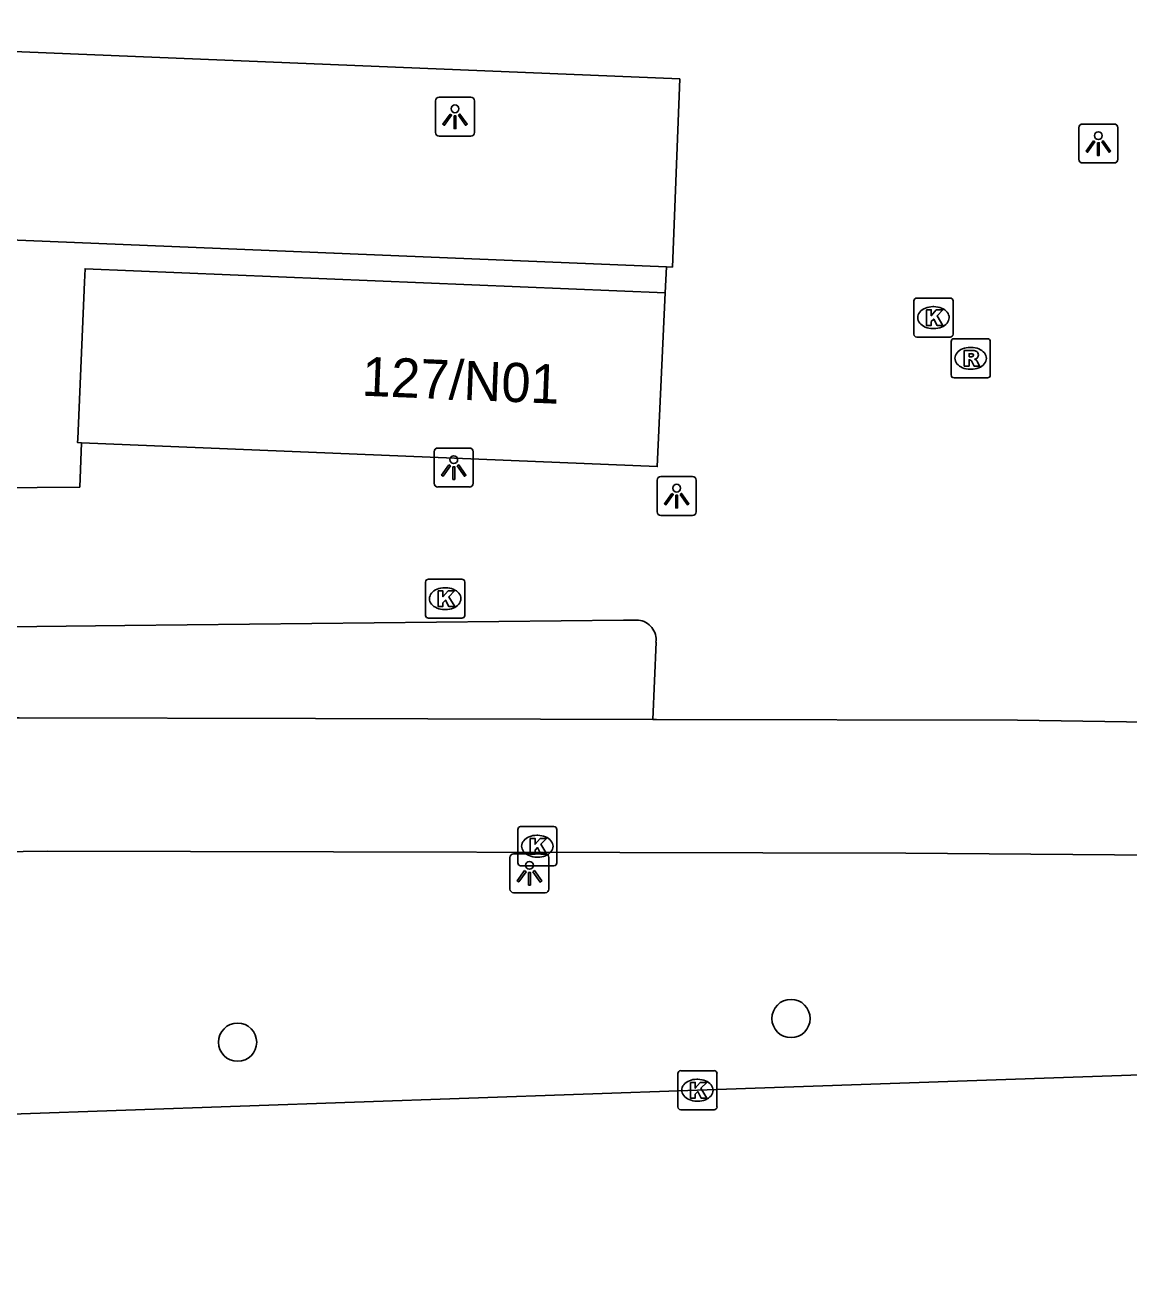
# Model space of a CAD drawing. Extents: x 160891 to 161384, y 386490 to 386907.
# Drawn here: x 161237.19 to 161265.4, y 386500.4 to 386532.6 of the extents above; entities that cross this region are included whole.
import ezdxf

# ---------------------------------------------------------------- set-up
doc = ezdxf.new("R2010")
doc.units = 0
for name, color, linetype in [('IMGEO_Boom', 7, 'Continuous'), ('IMGEO_Fietspad_gesloten', 7, 'Continuous'), ('IMGEO_Kolk', 7, 'Continuous'), ('IMGEO_Lichtpunt', 7, 'Continuous'), ('IMGEO_Pand', 7, 'Continuous'), ('IMGEO_Pand_nummerreeks', 7, 'Continuous'), ('IMGEO_Parkeervlak_open', 7, 'Continuous'), ('IMGEO_Rijbaan_regionaal_gesloten', 7, 'Continuous'), ('IMGEO_Rioolput', 7, 'Continuous'), ('IMGEO_Voetgangersgebied_open', 7, 'Continuous'), ('IMGEO_Voetpad_open', 7, 'Continuous')]:
    doc.layers.add(name, color=color, linetype=linetype)

msp = doc.modelspace()

# ---------------------------------------------------------------- linework, layer by layer
at = {"layer": 'IMGEO_Boom'}
for centre in [(161256.765, 386507.206), (161242.616, 386506.601)]:
    msp.add_circle(centre, 0.489, dxfattribs=at)
at = {"layer": 'IMGEO_Fietspad_gesloten'}
for points in [[(161253.233, 386514.853), (161244.609, 386514.875), (161237.032, 386514.894), (161236.549, 386514.895), (161233.821, 386514.854), (161231.599, 386514.82), (161230.845, 386514.809), (161227.787, 386514.763), (161226.292, 386514.741), (161221.75, 386514.672), (161219.333, 386514.636), (161214.527, 386514.564), (161214.131, 386514.554), (161212.923, 386514.523), (161205.423, 386514.331), (161205.404, 386514.331)], [(161306.554, 386513.058), (161267.578, 386514.754), (161262.551, 386514.831), (161253.325, 386514.853), (161253.233, 386514.853)], [(161109.839, 386506.955), (161116.836, 386508.035), (161123.035, 386508.931), (161127.225, 386509.29), (161167.964, 386510.348), (161215.734, 386511.569), (161215.758, 386511.159), (161222.805, 386511.284), (161237.753, 386511.488), (161259.697, 386511.429), (161267.164, 386511.376), (161306.097, 386509.668), (161311.73, 386509.285), (161311.776, 386509.705), (161313.071, 386509.592)]]:
    msp.add_lwpolyline(points, dxfattribs=at)
at = {"layer": 'IMGEO_Kolk'}
for p, q in [((161259.98, 386525.624), (161260.832, 386525.624)), ((161259.905, 386524.698), (161259.905, 386525.55)), ((161260.393, 386525.404), (161260.418, 386525.404)), ((161260.906, 386525.55), (161260.906, 386524.698)), ((161260.832, 386524.624), (161259.98, 386524.624)), ((161260.416, 386524.844), (161260.391, 386524.844)), ((161247.422, 386517.513), (161247.422, 386518.365)), ((161247.497, 386518.439), (161248.349, 386518.439)), ((161247.91, 386518.219), (161247.935, 386518.219)), ((161248.423, 386518.365), (161248.423, 386517.513)), ((161247.933, 386517.659), (161247.908, 386517.659)), ((161248.349, 386517.439), (161247.497, 386517.439)), ((161249.853, 386512.111), (161250.705, 386512.111)), ((161249.778, 386511.185), (161249.778, 386512.037)), ((161250.266, 386511.891), (161250.291, 386511.891)), ((161250.779, 386512.037), (161250.779, 386511.185)), ((161250.705, 386511.111), (161249.853, 386511.111)), ((161250.289, 386511.331), (161250.264, 386511.331)), ((161253.871, 386504.947), (161253.871, 386505.799)), ((161253.946, 386505.873), (161254.798, 386505.873)), ((161254.359, 386505.653), (161254.384, 386505.653)), ((161254.872, 386505.799), (161254.872, 386504.947)), ((161254.382, 386505.093), (161254.357, 386505.093)), ((161254.798, 386504.873), (161253.946, 386504.873))]:
    msp.add_line(p, q, dxfattribs=at)
for points in [[(161259.98, 386525.624), (161260.832, 386525.624)], [(161259.905, 386524.698), (161259.905, 386525.55)], [(161260.226, 386525.324), (161260.349, 386525.324), (161260.349, 386525.173), (161260.479, 386525.324), (161260.643, 386525.324), (161260.497, 386525.173), (161260.65, 386524.924), (161260.498, 386524.924), (161260.413, 386525.088), (161260.349, 386525.021), (161260.349, 386524.924), (161260.226, 386524.924), (161260.226, 386525.324)], [(161260.906, 386525.55), (161260.906, 386524.698)], [(161260.832, 386524.624), (161259.98, 386524.624)], [(161247.422, 386517.513), (161247.422, 386518.365)], [(161247.497, 386518.439), (161248.349, 386518.439)], [(161248.423, 386518.365), (161248.423, 386517.513)], [(161247.743, 386518.139), (161247.866, 386518.139), (161247.866, 386517.988), (161247.996, 386518.139), (161248.16, 386518.139), (161248.014, 386517.988), (161248.167, 386517.739), (161248.015, 386517.739), (161247.93, 386517.903), (161247.866, 386517.836), (161247.866, 386517.739), (161247.743, 386517.739), (161247.743, 386518.139)], [(161248.349, 386517.439), (161247.497, 386517.439)], [(161249.853, 386512.111), (161250.705, 386512.111)], [(161249.778, 386511.185), (161249.778, 386512.037)], [(161250.099, 386511.811), (161250.222, 386511.811), (161250.222, 386511.66), (161250.352, 386511.811), (161250.516, 386511.811), (161250.37, 386511.66), (161250.523, 386511.411), (161250.371, 386511.411), (161250.286, 386511.575), (161250.222, 386511.508), (161250.222, 386511.411), (161250.099, 386511.411), (161250.099, 386511.811)], [(161250.779, 386512.037), (161250.779, 386511.185)], [(161250.705, 386511.111), (161249.853, 386511.111)], [(161253.871, 386504.947), (161253.871, 386505.799)], [(161253.946, 386505.873), (161254.798, 386505.873)], [(161254.872, 386505.799), (161254.872, 386504.947)], [(161254.192, 386505.573), (161254.315, 386505.573), (161254.315, 386505.422), (161254.445, 386505.573), (161254.609, 386505.573), (161254.463, 386505.422), (161254.616, 386505.173), (161254.464, 386505.173), (161254.379, 386505.337), (161254.315, 386505.27), (161254.315, 386505.173), (161254.192, 386505.173), (161254.192, 386505.573)], [(161254.798, 386504.873), (161253.946, 386504.873)]]:
    msp.add_lwpolyline(points, dxfattribs=at)
for centre, start, end in [((161259.982, 386525.548), 91.552, 178.448), ((161259.982, 386525.548), 91.552, 178.448), ((161260.83, 386525.548), 1.552, 88.448), ((161260.83, 386525.548), 1.552, 88.448), ((161259.982, 386524.7), 181.552, 268.448), ((161259.982, 386524.7), 181.552, 268.448), ((161260.83, 386524.7), 271.552, 358.448), ((161260.83, 386524.7), 271.552, 358.448), ((161247.499, 386518.363), 91.552, 178.448), ((161247.499, 386518.363), 91.552, 178.448), ((161248.347, 386518.363), 1.552, 88.448), ((161248.347, 386518.363), 1.552, 88.448), ((161247.499, 386517.515), 181.552, 268.448), ((161247.499, 386517.515), 181.552, 268.448), ((161248.347, 386517.515), 271.552, 358.448), ((161248.347, 386517.515), 271.552, 358.448), ((161249.855, 386512.035), 91.552, 178.448), ((161249.855, 386512.035), 91.552, 178.448), ((161250.703, 386512.035), 1.552, 88.448), ((161250.703, 386512.035), 1.552, 88.448), ((161249.855, 386511.187), 181.552, 268.448), ((161249.855, 386511.187), 181.552, 268.448), ((161250.703, 386511.187), 271.552, 358.448), ((161250.703, 386511.187), 271.552, 358.448), ((161253.948, 386505.797), 91.552, 178.448), ((161253.948, 386505.797), 91.552, 178.448), ((161254.796, 386505.797), 1.552, 88.448), ((161254.796, 386505.797), 1.552, 88.448), ((161253.948, 386504.949), 181.552, 268.448), ((161253.948, 386504.949), 181.552, 268.448), ((161254.796, 386504.949), 271.552, 358.448), ((161254.796, 386504.949), 271.552, 358.448)]:
    msp.add_arc(centre, 0.0765, start, end, dxfattribs=at)
for centre, major_axis, ratio, start_param, end_param in [((161260.392, 386525.124), (-0.387, 0.002), 0.722429, 4.712389, 7.853982), ((161260.417, 386525.124), (-0.39, 0.002), 0.717154, 1.570796, 4.712389), ((161247.909, 386517.939), (-0.387, 0.002), 0.722429, 4.712389, 7.853982), ((161247.934, 386517.939), (-0.39, 0.002), 0.717154, 1.570796, 4.712389), ((161250.265, 386511.611), (-0.387, 0.002), 0.722429, 4.712389, 7.853982), ((161250.29, 386511.611), (-0.39, 0.002), 0.717154, 1.570796, 4.712389), ((161254.358, 386505.373), (-0.387, 0.002), 0.722429, 4.712389, 7.853982), ((161254.383, 386505.373), (-0.39, 0.002), 0.717154, 1.570796, 4.712389)]:
    msp.add_ellipse(centre, major_axis=major_axis, ratio=ratio, start_param=start_param, end_param=end_param, dxfattribs=at)
at = {"layer": 'IMGEO_Lichtpunt'}
for p, q in [((161248.577, 386530.759), (161247.769, 386530.759)), ((161248.577, 386530.759), (161247.769, 386530.759)), ((161247.675, 386530.664), (161247.675, 386529.857)), ((161247.675, 386530.664), (161247.675, 386529.857)), ((161248.671, 386529.857), (161248.671, 386530.664)), ((161248.671, 386529.857), (161248.671, 386530.664)), ((161264.123, 386529.978), (161264.123, 386529.171)), ((161264.123, 386529.978), (161264.123, 386529.171)), ((161265.025, 386530.073), (161264.217, 386530.073)), ((161265.025, 386530.073), (161264.217, 386530.073)), ((161265.119, 386529.171), (161265.119, 386529.978)), ((161265.119, 386529.171), (161265.119, 386529.978)), ((161247.769, 386529.763), (161248.577, 386529.763)), ((161247.769, 386529.763), (161248.577, 386529.763)), ((161264.217, 386529.077), (161265.025, 386529.077)), ((161264.217, 386529.077), (161265.025, 386529.077)), ((161248.546, 386521.79), (161247.738, 386521.79)), ((161248.546, 386521.79), (161247.738, 386521.79)), ((161247.644, 386521.695), (161247.644, 386520.888)), ((161247.644, 386521.695), (161247.644, 386520.888)), ((161248.64, 386520.888), (161248.64, 386521.695)), ((161248.64, 386520.888), (161248.64, 386521.695)), ((161247.738, 386520.794), (161248.546, 386520.794)), ((161247.738, 386520.794), (161248.546, 386520.794)), ((161253.343, 386520.966), (161253.343, 386520.159)), ((161253.343, 386520.966), (161253.343, 386520.159)), ((161254.245, 386521.061), (161253.437, 386521.061)), ((161254.245, 386521.061), (161253.437, 386521.061)), ((161254.339, 386520.159), (161254.339, 386520.966)), ((161254.339, 386520.159), (161254.339, 386520.966)), ((161253.437, 386520.065), (161254.245, 386520.065)), ((161253.437, 386520.065), (161254.245, 386520.065)), ((161250.481, 386511.418), (161249.673, 386511.418)), ((161250.481, 386511.418), (161249.673, 386511.418)), ((161249.579, 386511.323), (161249.579, 386510.516)), ((161249.579, 386511.323), (161249.579, 386510.516)), ((161250.575, 386510.516), (161250.575, 386511.323)), ((161250.575, 386510.516), (161250.575, 386511.323)), ((161249.673, 386510.422), (161250.481, 386510.422)), ((161249.673, 386510.422), (161250.481, 386510.422))]:
    msp.add_line(p, q, dxfattribs=at)
for points in [[(161248.049, 386530.328), (161248.088, 386530.3), (161247.9, 386530.038), (161247.862, 386530.065), (161248.049, 386530.328)], [(161248.151, 386530.28), (161248.198, 386530.28), (161248.198, 386529.958), (161248.151, 386529.958), (161248.151, 386530.28)], [(161248.261, 386530.3), (161248.299, 386530.327), (161248.486, 386530.065), (161248.447, 386530.037), (161248.261, 386530.3)], [(161264.497, 386529.642), (161264.536, 386529.614), (161264.348, 386529.352), (161264.31, 386529.379), (161264.497, 386529.642)], [(161264.599, 386529.594), (161264.646, 386529.594), (161264.646, 386529.272), (161264.599, 386529.272), (161264.599, 386529.594)], [(161264.709, 386529.614), (161264.747, 386529.641), (161264.934, 386529.379), (161264.895, 386529.351), (161264.709, 386529.614)], [(161248.018, 386521.359), (161248.057, 386521.331), (161247.869, 386521.069), (161247.831, 386521.096), (161248.018, 386521.359)], [(161248.12, 386521.311), (161248.167, 386521.311), (161248.167, 386520.989), (161248.12, 386520.989), (161248.12, 386521.311)], [(161248.23, 386521.331), (161248.268, 386521.358), (161248.455, 386521.096), (161248.416, 386521.068), (161248.23, 386521.331)], [(161253.717, 386520.63), (161253.756, 386520.602), (161253.568, 386520.34), (161253.53, 386520.367), (161253.717, 386520.63)], [(161253.819, 386520.582), (161253.866, 386520.582), (161253.866, 386520.26), (161253.819, 386520.26), (161253.819, 386520.582)], [(161253.929, 386520.602), (161253.967, 386520.629), (161254.154, 386520.367), (161254.115, 386520.339), (161253.929, 386520.602)], [(161249.953, 386510.987), (161249.992, 386510.959), (161249.804, 386510.697), (161249.766, 386510.724), (161249.953, 386510.987)], [(161250.055, 386510.939), (161250.102, 386510.939), (161250.102, 386510.617), (161250.055, 386510.617), (161250.055, 386510.939)], [(161250.165, 386510.959), (161250.203, 386510.986), (161250.39, 386510.724), (161250.351, 386510.696), (161250.165, 386510.959)]]:
    msp.add_lwpolyline(points, dxfattribs=at)
for centre in [(161248.174, 386530.462), (161264.622, 386529.776), (161248.143, 386521.493), (161253.842, 386520.764), (161250.078, 386511.121)]:
    msp.add_circle(centre, 0.0994, dxfattribs=at)
for centre, start, end in [((161247.769, 386530.664), 90, 180), ((161247.769, 386530.664), 90, 180), ((161248.577, 386530.664), 0, 90), ((161248.577, 386530.664), 0, 90), ((161247.769, 386529.857), 180, 270), ((161247.769, 386529.857), 180, 270), ((161248.577, 386529.857), 270, 0), ((161248.577, 386529.857), 270, 360), ((161264.217, 386529.978), 90, 180), ((161264.217, 386529.978), 90, 180), ((161265.025, 386529.978), 0, 90), ((161265.025, 386529.978), 0, 90), ((161264.217, 386529.171), 180, 270), ((161264.217, 386529.171), 180, 270), ((161265.025, 386529.171), 270, 0), ((161265.025, 386529.171), 270, 360), ((161247.738, 386521.695), 90, 180), ((161247.738, 386521.695), 90, 180), ((161248.546, 386521.695), 0, 90), ((161248.546, 386521.695), 0, 90), ((161247.738, 386520.888), 180, 270), ((161247.738, 386520.888), 180, 270), ((161248.546, 386520.888), 270, 0), ((161248.546, 386520.888), 270, 360), ((161253.437, 386520.966), 90, 180), ((161253.437, 386520.966), 90, 180), ((161254.245, 386520.966), 0, 90), ((161254.245, 386520.966), 0, 90), ((161253.437, 386520.159), 180, 270), ((161253.437, 386520.159), 180, 270), ((161254.245, 386520.159), 270, 0), ((161254.245, 386520.159), 270, 360), ((161249.673, 386511.323), 90, 180), ((161249.673, 386511.323), 90, 180), ((161250.481, 386511.323), 0, 90), ((161250.481, 386511.323), 0, 90), ((161249.673, 386510.516), 180, 270), ((161249.673, 386510.516), 180, 270), ((161250.481, 386510.516), 270, 0), ((161250.481, 386510.516), 270, 360)]:
    msp.add_arc(centre, 0.0946, start, end, dxfattribs=at)
at = {"layer": 'IMGEO_Pand'}
for points in [[(161238.627, 386521.923), (161238.527, 386521.927), (161238.531, 386522.021), (161238.703, 386526.033), (161238.718, 386526.371), (161253.549, 386525.76)], [(161253.549, 386525.76), (161253.343, 386521.315), (161238.627, 386521.923)]]:
    msp.add_lwpolyline(points, dxfattribs=at)
at = {"layer": 'IMGEO_Parkeervlak_open'}
msp.add_lwpolyline([(161253.58, 386526.42), (161253.732, 386526.414), (161253.921, 386531.225), (161220.471, 386532.599)], dxfattribs=at)
at = {"layer": 'IMGEO_Rijbaan_regionaal_gesloten'}
msp.add_lwpolyline([(161323.08, 386507.769), (161322.733, 386507.751), (161292.306, 386506.7), (161273.833, 386506.048), (161254.372, 386505.373), (161233.906, 386504.66), (161214.429, 386503.969), (161194.971, 386503.319), (161175.497, 386502.675), (161154.024, 386501.918), (161133.563, 386501.204), (161132.874, 386501.189), (161113.106, 386500.507), (161110.084, 386500.399)], dxfattribs=at)
at = {"layer": 'IMGEO_Rioolput'}
for p, q in [((161260.857, 386523.657), (161260.857, 386524.509)), ((161260.932, 386524.583), (161261.784, 386524.583)), ((161261.345, 386524.363), (161261.37, 386524.363)), ((161261.858, 386524.509), (161261.858, 386523.657)), ((161261.368, 386523.803), (161261.343, 386523.803)), ((161261.784, 386523.583), (161260.932, 386523.583))]:
    msp.add_line(p, q, dxfattribs=at)
for points in [[(161260.857, 386523.657), (161260.857, 386524.509)], [(161260.932, 386524.583), (161261.784, 386524.583)], [(161261.858, 386524.509), (161261.858, 386523.657)], [(161261.446, 386524.281), (161261.194, 386524.283), (161261.194, 386523.883)], [(161261.194, 386523.883), (161261.318, 386523.883), (161261.318, 386524.045), (161261.329, 386524.045)], [(161261.372, 386524.202), (161261.318, 386524.202), (161261.318, 386524.121)], [(161261.318, 386524.121), (161261.37, 386524.121)], [(161261.376, 386524.016), (161261.447, 386523.883), (161261.587, 386523.883), (161261.522, 386524.009)], [(161261.784, 386523.583), (161260.932, 386523.583)]]:
    msp.add_lwpolyline(points, dxfattribs=at)
for centre, radius, start, end in [((161260.934, 386524.507), 0.0765, 91.552, 178.448), ((161260.934, 386524.507), 0.0765, 91.552, 178.448), ((161261.782, 386524.507), 0.0765, 1.552, 88.448), ((161261.782, 386524.507), 0.0765, 1.552, 88.448), ((161261.328, 386523.992), 0.0533, 26.0293, 88.6989), ((161261.354, 386524.31), 0.19, 274.7715, 282.9687), ((161261.378, 386524.106), 0.0964, 77.0061, 93.1865), ((161261.392, 386524.163), 0.0378, 276.6634, 79.6772), ((161261.445, 386524.171), 0.109, 350.3612, 89.416), ((161261.443, 386524.171), 0.112, 277.5842, 350.9817), ((161261.427, 386523.956), 0.108, 29.5134, 73.7905), ((161260.934, 386523.659), 0.0765, 181.552, 268.448), ((161260.934, 386523.659), 0.0765, 181.552, 268.448), ((161261.782, 386523.659), 0.0765, 271.552, 358.448), ((161261.782, 386523.659), 0.0765, 271.552, 358.448)]:
    msp.add_arc(centre, radius, start, end, dxfattribs=at)
for centre, major_axis, ratio, start_param, end_param in [((161261.344, 386524.083), (-0.387, 0.002), 0.722429, 4.712389, 7.853982), ((161261.369, 386524.083), (-0.39, 0.002), 0.717154, 1.570796, 4.712389)]:
    msp.add_ellipse(centre, major_axis=major_axis, ratio=ratio, start_param=start_param, end_param=end_param, dxfattribs=at)
at = {"layer": 'IMGEO_Voetgangersgebied_open'}
for points in [[(161205.844, 386516.883), (161205.917, 386516.886), (161206.016, 386516.884), (161206.921, 386516.896), (161221.767, 386517.056), (161233.722, 386517.186), (161239.735, 386517.251), (161252.478, 386517.39), (161252.863, 386517.39)], [(161253.313, 386516.825), (161253.233, 386514.853)]]:
    msp.add_lwpolyline(points, dxfattribs=at)
msp.add_arc((161252.806, 386516.883), 0.51, 353.443, 83.6289, dxfattribs=at)
at = {"layer": 'IMGEO_Voetpad_open'}
for points in [[(161236.584, 386527.124), (161253.58, 386526.42)], [(161253.549, 386525.76), (161253.58, 386526.42)], [(161236.366, 386520.764), (161237.489, 386520.777), (161238.58, 386520.79), (161238.627, 386521.923)]]:
    msp.add_lwpolyline(points, dxfattribs=at)

# ---------------------------------------------------------------- texts
at = {"layer": 'IMGEO_Pand_nummerreeks'}
msp.add_text('127/N01', height=1, rotation=357.6337, dxfattribs=at).set_placement((161245.778, 386523.129))

doc.saveas('drawing.dxf')
